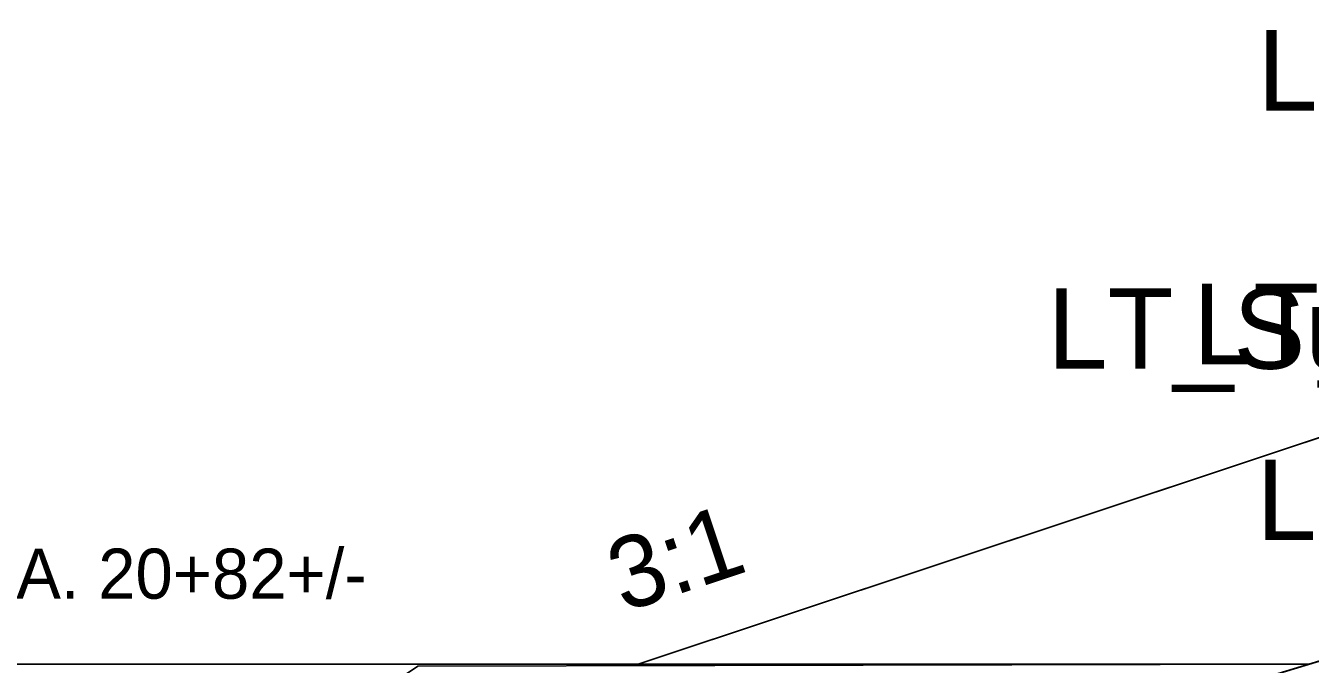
# Model space of a CAD drawing. Extents: x -14026 to 1303, y -10 to 9533.
# Drawn here: x 106.57 to 124.5, y 7005.4 to 7014.32 of the extents above; entities that cross this region are included whole.
import ezdxf

# ---------------------------------------------------------------- set-up
doc = ezdxf.new("R2010")
doc.units = 0
for name, color, linetype in [('Exist XS Ground Line', 7, 'Continuous'), ('Old_Level_10', 7, 'Continuous'), ('Prop CMT Slope Grass', 7, 'Continuous'), ('Prop CMT Subgrade Earthwork', 7, 'Continuous'), ('Prop XS Earthwork Shape', 7, 'Continuous'), ('Prop XS Side Slope Text', 7, 'Continuous'), ('Scratch_Level_0', 7, 'Continuous'), ('Scratch_Level_3', 7, 'Continuous')]:
    doc.layers.add(name, color=color, linetype=linetype)

msp = doc.modelspace()

# ---------------------------------------------------------------- linework, layer by layer
at = {"layer": 'Exist XS Ground Line'}
msp.add_lwpolyline([(76.627, 7001.596), (82.763, 7000.732), (89.575, 7000.89), (99.782, 7000.855), (110.046, 7001.415), (110.502, 7001.459), (119.611, 7002.343), (120.213, 7003.277), (121.024, 7004.352), (128.864, 7006.731)], dxfattribs=at)
at = {"layer": 'Old_Level_10'}
msp.add_lwpolyline([(110.046, 7001.415), (105.753, 7001.181), (112.043, 7005.374), (124.478, 7005.4), (121.024, 7004.352), (120.213, 7003.277), (119.611, 7002.343)], close=True, dxfattribs=at)
at = {"layer": 'Prop CMT Slope Grass'}
msp.add_line((115.121, 7005.4), (124.478, 7005.4), dxfattribs=at)
msp.add_lwpolyline([(130, 7010.355), (115.121, 7005.4)], dxfattribs=at)
at = {"layer": 'Prop CMT Subgrade Earthwork'}
msp.add_line((115.121, 7005.4), (124.478, 7005.4), dxfattribs=at)
msp.add_lwpolyline([(127.514, 7009.527), (115.121, 7005.4)], dxfattribs=at)
at = {"layer": 'Prop XS Earthwork Shape'}
msp.add_lwpolyline([(130, 7010.355), (115.121, 7005.4), (124.478, 7005.4), (128.864, 7006.731)], dxfattribs=at)
msp.add_lwpolyline([(130, 7009.589), (127.514, 7009.527), (115.121, 7005.4), (124.478, 7005.4), (128.864, 7006.731), (132.294, 7007.798), (134.892, 7008.507), (139.386, 7009.612), (141.215, 7009.527), (143.121, 7009.593), (143.761, 7009.708), (144.983, 7009.963), (138, 7009.789), (132.017, 7009.639)], close=True, dxfattribs=at)
at = {"layer": 'Scratch_Level_3'}
msp.add_line((124.478, 7005.4), (101.852, 7005.4), dxfattribs=at)

# ---------------------------------------------------------------- texts
at = {"layer": 'Old_Level_10'}
msp.add_text('BEGIN ROCK EMBANKMENT STABILITY @ STA. 20+82+/-', height=0.7, dxfattribs=at).set_placement((86.087, 7006.316))
at = {"layer": 'Prop XS Side Slope Text'}
msp.add_text('3:1', height=1, rotation=18.4178, dxfattribs=at).set_placement((114.912, 7006.121))
at = {"layer": 'Scratch_Level_0'}
for s, p in [('LT_GR_Graphics Out 03', (123.765, 7013.134)), ('LT_Sub_Graded_Tie', (120.834, 7009.527)), ('LT_Sub_Graded_CTL', (122.866, 7009.589)), ('LT_GR_Graphics Out 04', (123.751, 7007.134))]:
    msp.add_text(s, height=1.125, dxfattribs=at).set_placement(p)

doc.saveas('drawing.dxf')
